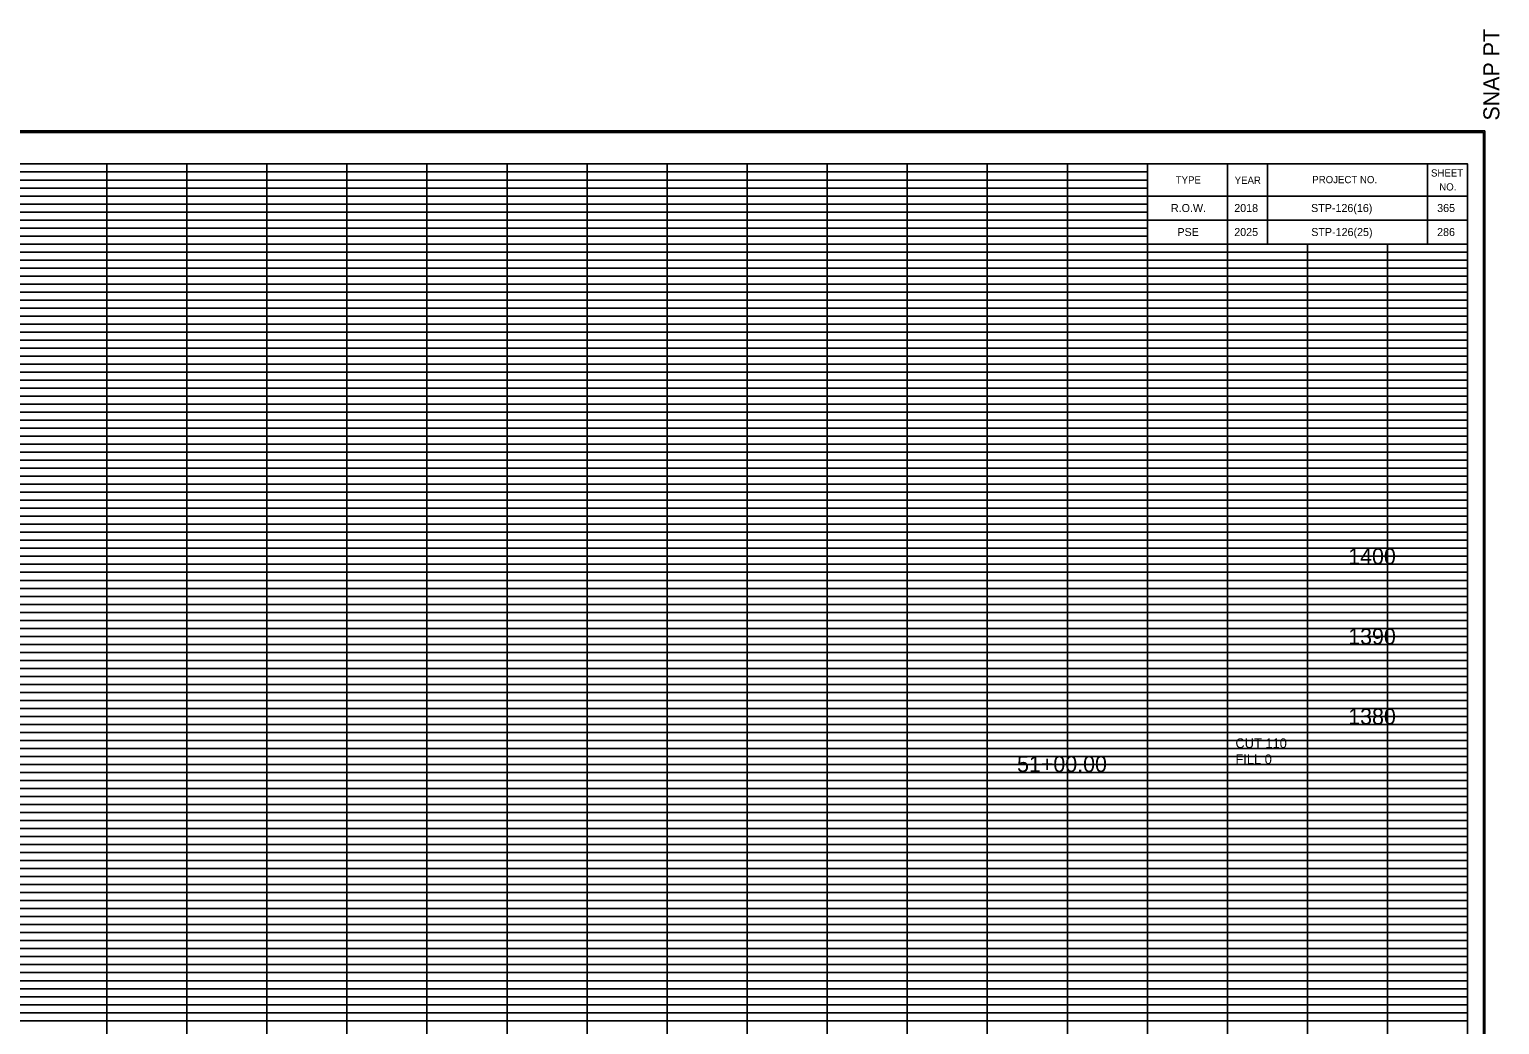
# Model space of a CAD drawing. Extents: x 980 to 1324, y 978 to 1497.
# Drawn here: x 1140.3 to 1324, y 1102.5 to 1226.8 of the extents above; entities that cross this region are included whole.
import ezdxf

# ---------------------------------------------------------------- set-up
doc = ezdxf.new("R2010")
doc.units = 0
for name, color, linetype in [('DESIGN - SCRATCH - User 1', 7, 'Continuous'), ('DESIGN - SHEET - Corner Text', 7, 'Continuous'), ('DESIGN - SHEET - Light Grid', 7, 'Continuous'), ('DESIGN - SHEET - Linework', 7, 'Continuous'), ('DESIGN - SHEET - Plot Shape', 7, 'Continuous'), ('DESIGN - TYPICAL - Text', 7, 'Continuous')]:
    doc.layers.add(name, color=color, linetype=linetype)

# ---------------------------------------------------------------- blocks, each defined once
blk = doc.blocks.new('XSTSHT')
at = {"layer": 'DESIGN - SCRATCH - User 1'}
for p, q in [((28.5, 20.45), (28.5, 20.45)), ((29.24, 20.45), (29.24, 20.45)), ((30.49, 20.45), (30.49, 20.45)), ((31.74, 20.45), (31.74, 20.45)), ((28.5, 20.15), (28.5, 20.15)), ((29.24, 20.15), (29.24, 20.15)), ((30.49, 20.15), (30.49, 20.15)), ((31.74, 20.15), (31.74, 20.15))]:
    blk.add_line(p, q, dxfattribs=at)
at = {"layer": 'DESIGN - SHEET - Light Grid'}
for p, q in [((8, 20.9), (16, 20.9)), ((8, 20.8), (16, 20.8)), ((16, 20.9), (24, 20.9)), ((16, 20.8), (24, 20.8)), ((24, 20.9), (28, 20.9)), ((24, 20.8), (28, 20.8)), ((8, 20.7), (16, 20.7)), ((8, 20.6), (16, 20.6)), ((16, 20.7), (24, 20.7)), ((16, 20.6), (24, 20.6)), ((24, 20.7), (28, 20.7)), ((24, 20.6), (28, 20.6)), ((8, 20.5), (16, 20.5)), ((8, 20.4), (16, 20.4)), ((16, 20.5), (24, 20.5)), ((16, 20.4), (24, 20.4)), ((24, 20.5), (28, 20.5)), ((24, 20.4), (28, 20.4)), ((8, 20.3), (16, 20.3)), ((16, 20.3), (24, 20.3)), ((24, 20.3), (28, 20.3)), ((8, 20.2), (16, 20.2)), ((8, 20.1), (16, 20.1)), ((16, 20.2), (24, 20.2)), ((16, 20.1), (24, 20.1)), ((24, 20.2), (28, 20.2)), ((24, 20.1), (28, 20.1)), ((8, 19.9), (16, 19.9)), ((16, 19.9), (24, 19.9)), ((24, 19.9), (32, 19.9)), ((8, 19.8), (16, 19.8)), ((8, 19.7), (16, 19.7)), ((16, 19.8), (24, 19.8)), ((16, 19.7), (24, 19.7)), ((24, 19.8), (32, 19.8)), ((24, 19.7), (32, 19.7)), ((8, 19.6), (16, 19.6)), ((8, 19.5), (16, 19.5)), ((16, 19.6), (24, 19.6)), ((16, 19.5), (24, 19.5)), ((24, 19.6), (32, 19.6)), ((24, 19.5), (32, 19.5)), ((8, 19.4), (16, 19.4)), ((8, 19.3), (16, 19.3)), ((16, 19.4), (24, 19.4)), ((16, 19.3), (24, 19.3)), ((24, 19.4), (32, 19.4)), ((24, 19.3), (32, 19.3)), ((8, 19.2), (16, 19.2)), ((16, 19.2), (24, 19.2)), ((24, 19.2), (32, 19.2)), ((8, 19.1), (16, 19.1)), ((16, 19.1), (24, 19.1)), ((24, 19.1), (32, 19.1)), ((8, 18.9), (16, 18.9)), ((8, 18.8), (16, 18.8)), ((16, 18.9), (24, 18.9)), ((16, 18.8), (24, 18.8)), ((24, 18.9), (32, 18.9)), ((24, 18.8), (32, 18.8)), ((8, 18.7), (16, 18.7)), ((8, 18.6), (16, 18.6)), ((16, 18.7), (24, 18.7)), ((16, 18.6), (24, 18.6)), ((24, 18.7), (32, 18.7)), ((24, 18.6), (32, 18.6)), ((8, 18.5), (16, 18.5)), ((8, 18.4), (16, 18.4)), ((16, 18.5), (24, 18.5)), ((16, 18.4), (24, 18.4)), ((24, 18.5), (32, 18.5)), ((24, 18.4), (32, 18.4)), ((8, 18.3), (16, 18.3)), ((8, 18.2), (16, 18.2)), ((16, 18.3), (24, 18.3)), ((16, 18.2), (24, 18.2)), ((24, 18.3), (32, 18.3)), ((24, 18.2), (32, 18.2)), ((8, 18.1), (16, 18.1)), ((16, 18.1), (24, 18.1)), ((24, 18.1), (32, 18.1)), ((8, 17.9), (16, 17.9)), ((16, 17.9), (24, 17.9)), ((24, 17.9), (32, 17.9)), ((8, 17.8), (16, 17.8)), ((8, 17.7), (16, 17.7)), ((16, 17.8), (24, 17.8)), ((16, 17.7), (24, 17.7)), ((24, 17.8), (32, 17.8)), ((24, 17.7), (32, 17.7)), ((8, 17.6), (16, 17.6)), ((8, 17.5), (16, 17.5)), ((16, 17.6), (24, 17.6)), ((16, 17.5), (24, 17.5)), ((24, 17.6), (32, 17.6)), ((24, 17.5), (32, 17.5)), ((8, 17.4), (16, 17.4)), ((8, 17.3), (16, 17.3)), ((16, 17.4), (24, 17.4)), ((16, 17.3), (24, 17.3)), ((24, 17.4), (32, 17.4)), ((24, 17.3), (32, 17.3)), ((8, 17.2), (16, 17.2)), ((8, 17.1), (16, 17.1)), ((16, 17.2), (24, 17.2)), ((16, 17.1), (24, 17.1)), ((24, 17.2), (32, 17.2)), ((24, 17.1), (32, 17.1)), ((8, 16.9), (16, 16.9)), ((16, 16.9), (24, 16.9)), ((24, 16.9), (32, 16.9)), ((8, 16.8), (16, 16.8)), ((16, 16.8), (24, 16.8)), ((24, 16.8), (32, 16.8)), ((8, 16.7), (16, 16.7)), ((8, 16.6), (16, 16.6)), ((16, 16.7), (24, 16.7)), ((16, 16.6), (24, 16.6)), ((24, 16.7), (32, 16.7)), ((24, 16.6), (32, 16.6)), ((8, 16.5), (16, 16.5)), ((8, 16.4), (16, 16.4)), ((16, 16.5), (24, 16.5)), ((16, 16.4), (24, 16.4)), ((24, 16.5), (32, 16.5)), ((24, 16.4), (32, 16.4)), ((8, 16.3), (16, 16.3)), ((8, 16.2), (16, 16.2)), ((16, 16.3), (24, 16.3)), ((16, 16.2), (24, 16.2)), ((24, 16.3), (32, 16.3)), ((24, 16.2), (32, 16.2)), ((8, 16.1), (16, 16.1)), ((16, 16.1), (24, 16.1)), ((24, 16.1), (32, 16.1)), ((8, 15.9), (16, 15.9)), ((8, 15.8), (16, 15.8)), ((16, 15.9), (24, 15.9)), ((16, 15.8), (24, 15.8)), ((24, 15.9), (32, 15.9)), ((24, 15.8), (32, 15.8)), ((8, 15.7), (16, 15.7)), ((16, 15.7), (24, 15.7)), ((24, 15.7), (32, 15.7)), ((8, 15.6), (16, 15.6)), ((8, 15.5), (16, 15.5)), ((16, 15.6), (24, 15.6)), ((16, 15.5), (24, 15.5)), ((24, 15.6), (32, 15.6)), ((24, 15.5), (32, 15.5)), ((8, 15.4), (16, 15.4)), ((8, 15.3), (16, 15.3)), ((16, 15.4), (24, 15.4)), ((16, 15.3), (24, 15.3)), ((24, 15.4), (32, 15.4)), ((24, 15.3), (32, 15.3)), ((8, 15.2), (16, 15.2)), ((8, 15.1), (16, 15.1)), ((16, 15.2), (24, 15.2)), ((16, 15.1), (24, 15.1)), ((24, 15.2), (32, 15.2)), ((24, 15.1), (32, 15.1)), ((8, 14.9), (16, 14.9)), ((16, 14.9), (24, 14.9)), ((24, 14.9), (32, 14.9)), ((8, 14.8), (16, 14.8)), ((8, 14.7), (16, 14.7)), ((16, 14.8), (24, 14.8)), ((16, 14.7), (24, 14.7)), ((24, 14.8), (32, 14.8)), ((24, 14.7), (32, 14.7)), ((8, 14.6), (16, 14.6)), ((16, 14.6), (24, 14.6)), ((24, 14.6), (32, 14.6)), ((8, 14.5), (16, 14.5)), ((8, 14.4), (16, 14.4)), ((16, 14.5), (24, 14.5)), ((16, 14.4), (24, 14.4)), ((24, 14.5), (32, 14.5)), ((24, 14.4), (32, 14.4)), ((8, 14.3), (16, 14.3)), ((8, 14.2), (16, 14.2)), ((16, 14.3), (24, 14.3)), ((16, 14.2), (24, 14.2)), ((24, 14.3), (32, 14.3)), ((24, 14.2), (32, 14.2)), ((8, 14.1), (16, 14.1)), ((16, 14.1), (24, 14.1)), ((24, 14.1), (32, 14.1)), ((8, 13.9), (16, 13.9)), ((8, 13.8), (16, 13.8)), ((16, 13.9), (24, 13.9)), ((16, 13.8), (24, 13.8)), ((24, 13.9), (32, 13.9)), ((24, 13.8), (32, 13.8)), ((8, 13.7), (16, 13.7)), ((8, 13.6), (16, 13.6)), ((16, 13.7), (24, 13.7)), ((16, 13.6), (24, 13.6)), ((24, 13.7), (32, 13.7)), ((24, 13.6), (32, 13.6)), ((8, 13.5), (16, 13.5)), ((16, 13.5), (24, 13.5)), ((24, 13.5), (32, 13.5)), ((8, 13.4), (16, 13.4)), ((8, 13.3), (16, 13.3)), ((16, 13.4), (24, 13.4)), ((16, 13.3), (24, 13.3)), ((24, 13.4), (32, 13.4)), ((24, 13.3), (32, 13.3)), ((8, 13.2), (16, 13.2)), ((8, 13.1), (16, 13.1)), ((16, 13.2), (24, 13.2)), ((16, 13.1), (24, 13.1)), ((24, 13.2), (32, 13.2)), ((24, 13.1), (32, 13.1)), ((8, 12.9), (16, 12.9)), ((16, 12.9), (24, 12.9)), ((24, 12.9), (32, 12.9)), ((8, 12.8), (16, 12.8)), ((8, 12.7), (16, 12.7)), ((16, 12.8), (24, 12.8)), ((16, 12.7), (24, 12.7)), ((24, 12.8), (32, 12.8)), ((24, 12.7), (32, 12.7)), ((8, 12.6), (16, 12.6)), ((8, 12.5), (16, 12.5)), ((16, 12.6), (24, 12.6)), ((16, 12.5), (24, 12.5)), ((24, 12.6), (32, 12.6)), ((24, 12.5), (32, 12.5)), ((8, 12.4), (16, 12.4)), ((16, 12.4), (24, 12.4)), ((24, 12.4), (32, 12.4)), ((8, 12.3), (16, 12.3)), ((8, 12.2), (16, 12.2)), ((16, 12.3), (24, 12.3)), ((16, 12.2), (24, 12.2)), ((24, 12.3), (32, 12.3)), ((24, 12.2), (32, 12.2)), ((8, 12.1), (16, 12.1)), ((16, 12.1), (24, 12.1)), ((24, 12.1), (32, 12.1)), ((8, 11.9), (16, 11.9)), ((8, 11.8), (16, 11.8)), ((16, 11.9), (24, 11.9)), ((16, 11.8), (24, 11.8)), ((24, 11.9), (32, 11.9)), ((24, 11.8), (32, 11.8)), ((8, 11.7), (16, 11.7)), ((8, 11.6), (16, 11.6)), ((16, 11.7), (24, 11.7)), ((16, 11.6), (24, 11.6)), ((24, 11.7), (32, 11.7)), ((24, 11.6), (32, 11.6)), ((8, 11.5), (16, 11.5)), ((8, 11.4), (16, 11.4)), ((16, 11.5), (24, 11.5)), ((16, 11.4), (24, 11.4)), ((24, 11.5), (32, 11.5)), ((24, 11.4), (32, 11.4)), ((8, 11.3), (16, 11.3)), ((16, 11.3), (24, 11.3)), ((24, 11.3), (32, 11.3)), ((8, 11.2), (16, 11.2)), ((8, 11.1), (16, 11.1)), ((16, 11.2), (24, 11.2)), ((16, 11.1), (24, 11.1)), ((24, 11.2), (32, 11.2)), ((24, 11.1), (32, 11.1)), ((8, 10.9), (16, 10.9)), ((16, 10.9), (24, 10.9)), ((24, 10.9), (32, 10.9)), ((8, 10.8), (16, 10.8)), ((8, 10.7), (16, 10.7)), ((16, 10.8), (24, 10.8)), ((16, 10.7), (24, 10.7)), ((24, 10.8), (32, 10.8)), ((24, 10.7), (32, 10.7)), ((8, 10.6), (16, 10.6)), ((8, 10.5), (16, 10.5)), ((16, 10.6), (24, 10.6)), ((16, 10.5), (24, 10.5)), ((24, 10.6), (32, 10.6)), ((24, 10.5), (32, 10.5)), ((8, 10.4), (16, 10.4)), ((8, 10.3), (16, 10.3)), ((16, 10.4), (24, 10.4)), ((16, 10.3), (24, 10.3)), ((24, 10.4), (32, 10.4)), ((24, 10.3), (32, 10.3))]:
    blk.add_line(p, q, dxfattribs=at)
at = {"layer": 'DESIGN - SHEET - Linework'}
for p, q in [((-1.823, 21.414), (32.217, 21.414)), ((32.217, 21.414), (32.217, -0.414)), ((15, 0), (15, 21)), ((16, 0), (16, 21)), ((17, 0), (17, 21)), ((18, 0), (18, 21)), ((19, 0), (19, 21)), ((20, 0), (20, 21)), ((21, 0), (21, 21)), ((22, 0), (22, 21)), ((23, 0), (23, 21)), ((24, 0), (24, 21)), ((25, 0), (25, 21)), ((26, 0), (26, 21)), ((27, 0), (27, 21)), ((0, 20), (28, 20)), ((28, 0), (28, 20)), ((29, 0), (29, 20)), ((30, 0), (30, 20)), ((31, 0), (31, 20)), ((0, 19), (32, 19)), ((0, 18), (32, 18)), ((0, 17), (32, 17)), ((0, 16), (32, 16)), ((0, 15), (32, 15)), ((0, 14), (32, 14)), ((0, 13), (32, 13)), ((0, 12), (32, 12)), ((0, 11), (32, 11))]:
    blk.add_line(p, q, dxfattribs=at)
for points in [[(0, 21), (0, 0), (32, 0), (32, 21), (0, 21)], [(28, 21), (28, 20), (32, 20), (32, 21), (31.5, 21), (31.5, 20), (29.5, 20), (29.5, 21), (29, 21), (29, 20), (32, 20), (28, 20), (28, 20.3), (32, 20.3), (32, 20.6), (28, 20.6)]]:
    blk.add_lwpolyline(points, dxfattribs=at)
at = {"layer": 'DESIGN - SHEET - Plot Shape'}
for points in [[(-1.803, 21.394), (32.197, 21.394), (32.197, -0.394), (-1.803, -0.394)], [(-0.85, 21), (32, 21), (32, -0.25), (-0.85, -0.25)]]:
    blk.add_lwpolyline(points, close=True, dxfattribs=at)
at = {"layer": 'DESIGN - SHEET - Corner Text'}
blk.add_text('  SNAP PT', height=0.2, rotation=90, dxfattribs=at).set_placement((32.397, 21.394))
for s, p in [('TYPE', (28.354, 20.756)), ('YEAR', (29.09, 20.752)), ('PROJECT NO.', (30.06, 20.76)), ('SHEET', (31.543, 20.843)), ('NO.', (31.646, 20.669))]:
    blk.add_text(s, height=0.09, dxfattribs=at).set_placement(p)

msp = doc.modelspace()

# ---------------------------------------------------------------- linework, layer by layer
at = {"layer": 'DESIGN - SHEET - Plot Shape'}
msp.add_lwpolyline([(991.5, 997.5), (1320, 997.5), (1320, 1210), (991.5, 1210)], close=True, dxfattribs=at)

# ---------------------------------------------------------------- block references
at = {"layer": 'DESIGN - TYPICAL - Text', "xscale": 10, "yscale": 10}
msp.add_blockref('XSTSHT', (1000, 1000), dxfattribs=at)

# ---------------------------------------------------------------- texts
at = {"layer": 'DESIGN - SHEET - Corner Text'}
for s, p in [('R.O.W.', (1282.94, 1204)), ('2018', (1290.85, 1204)), ('STP-126(16)', (1300.45, 1204)), ('365', (1316.2, 1204)), ('PSE', (1283.75, 1201)), ('2025', (1290.85, 1201)), ('STP-126(25)', (1300.47, 1201)), ('286', (1316.19, 1201))]:
    msp.add_text(s, height=1, dxfattribs=at).set_placement(p)
at = {"layer": 'DESIGN - TYPICAL - Text'}
for s, height, p in [('     1400     ', 2, (1301.37, 1160)), ('     1390     ', 2, (1301.37, 1150)), ('     1380     ', 2, (1301.37, 1140)), ('CUT 110', 1.2, (1291, 1137.06)), ('     51+00.00     ', 2, (1260, 1134.06)), ('FILL 0', 1.2, (1291, 1135.06))]:
    msp.add_text(s, height=height, dxfattribs=at).set_placement(p)

doc.saveas('drawing.dxf')
